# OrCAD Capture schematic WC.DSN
size A; company: mycompany; note: line1; note: line 2
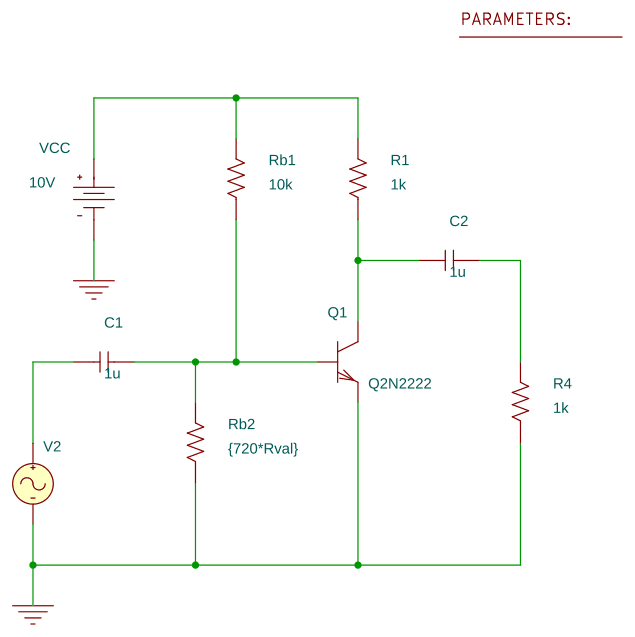
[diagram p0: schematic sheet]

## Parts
1  PARAM
C1  1u  [RAD/CK05]
C2  1u  [RAD/CK05]
Q1  Q2N2222  [TO18]
R1  1k  [AX/RC05]
R4  1k  [AX/RC05]
Rb1  10k  [AX/RC05]
Rb2  {720*Rval}
V2  VAC
VCC  VDC

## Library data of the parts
1 = PARAM
C1 C2 = C
Q1 = Q2N2222
R1 R4 Rb1 = R
Rb2 = Rbreak
V2 = VAC
VCC = VDC: DC: 10V

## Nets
0: Q1.1(e) R4.1 Rb2.1 V2.2(-) VCC.1(-)
N00216: C1.2 Q1.2(b) Rb1.1 Rb2.0(2)
N00248: R1.2 Rb1.2 VCC.0(+)
N00272: C2.1 Q1.3(c) R1.1
N00326: C2.2 R4.2
N00453: C1.1 V2.1(+)
